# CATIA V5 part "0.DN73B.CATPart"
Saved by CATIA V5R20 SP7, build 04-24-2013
Part number: 0.DN73B
Material "Nessuno"
Bounding box of the stored display mesh (mm): x -14.589 to 149.213, y -143.683 to 0, z -56.919 to 41.584
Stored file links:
  C:\Users\designer2\Desktop\Ottobre 2022\25-10-2022\04\Yori Evo 48V\0.DN73B.CATPart
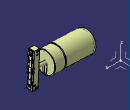
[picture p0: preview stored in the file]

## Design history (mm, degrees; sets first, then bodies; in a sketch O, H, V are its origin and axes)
AxisSystem1: origin (0, 0, 0), X (1, 0, 0), Y (0, 1, 0), Z (0, 0, 1)
Set1
  DatumSurface1
Body1 (main body), material "Nessuno"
